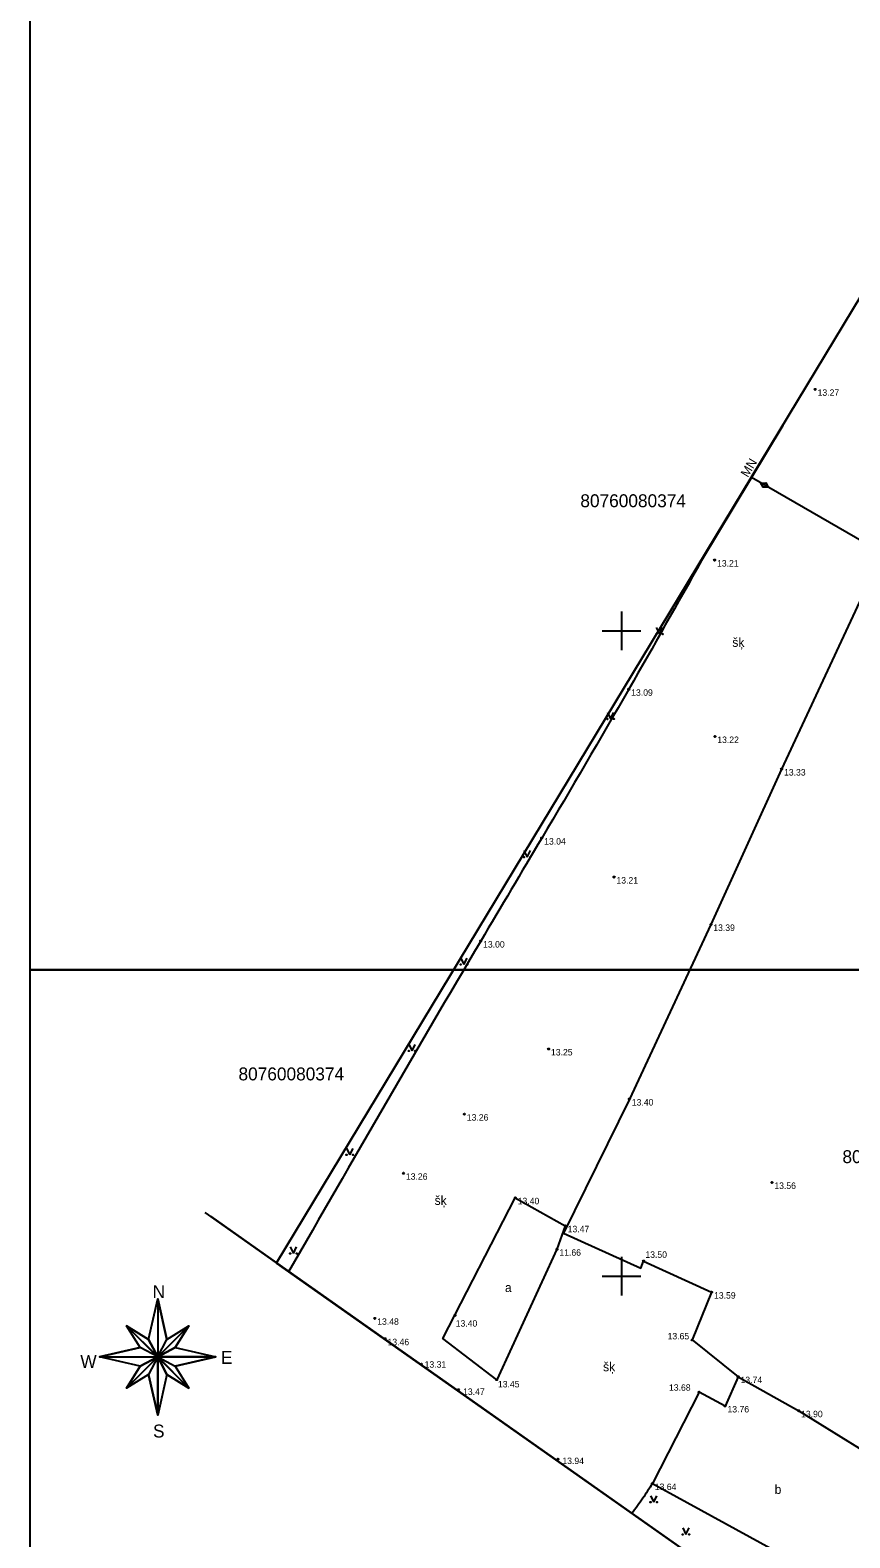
# Model space of a CAD drawing. Extents: x 503904 to 504094, y 304688 to 304960.
# Drawn here: x 503904.2 to 503967.7, y 304779.7 to 304896.6 of the extents above; entities that cross this region are included whole.
import ezdxf

# ---------------------------------------------------------------- set-up
doc = ezdxf.new("R2010")
doc.units = 0
for name, color, linetype in [('BUVE_EKAS_####_####_#', 7, 'Continuous'), ('BUVE_EKAS_RAKS_TKST_#', 7, 'Continuous'), ('CELI_CMAL_####_####_#', 7, 'Continuous'), ('CELI_CSEG_####_TKST_#', 7, 'Continuous'), ('CELI_TAKA_####_####_#', 7, 'Continuous'), ('GEOD_ELEM_####_####_#', 7, 'Continuous'), ('RAMI_PLAN_####_TKST_#', 7, 'Continuous'), ('RAMI_UZMR_####_####_#', 7, 'Continuous'), ('RELJ_AATZ_####_TKST_#', 7, 'Continuous'), ('RELJ_ELEM_####_####_#', 7, 'Continuous'), ('ROBZ_UZMR_####_####_#', 7, 'Continuous'), ('ROBZ_UZMR_####_TKST_#', 7, 'Continuous'), ('SAKT_ELEM_####_####_#', 7, 'Continuous'), ('SAKT_VADP_KABE_####_#', 7, 'Continuous'), ('TERT_ELEM_####_####_#', 7, 'Continuous')]:
    doc.layers.add(name, color=color, linetype=linetype)

msp = doc.modelspace()

# ---------------------------------------------------------------- linework, layer by layer
at = {"layer": 'BUVE_EKAS_####_####_#'}
for p, q in [((503962.51, 304865.92), (503956.21, 304855.46)), ((503962.5, 304865.93), (503962.51, 304865.92)), ((503956.21, 304855.46), (503956.18, 304855.48))]:
    msp.add_line(p, q, dxfattribs=at)
at = {"layer": 'CELI_CMAL_####_####_#'}
for points in [[(503988.45, 304902.16), (503990.82, 304901.05), (503991.1, 304895.95), (503989.73, 304890.94), (503987.1, 304886.1), (503981.04, 304876.47), (503973.97, 304864.11), (503962.41, 304839.3), (503956.93, 304827.26), (503950.62, 304813.73), (503945.51, 304803.34), (503951.5, 304800.63), (503951.72, 304801.18), (503956.99, 304798.77), (503955.48, 304795.07), (503959.04, 304792.22), (503963.73, 304789.58), (503971.68, 304784.66)], [(503941.78, 304806.08), (503945.65, 304803.91), (503945.01, 304802.09), (503940.34, 304791.99), (503936.17, 304795.17), (503941.78, 304806.08)], [(503959.04, 304792.22), (503958.03, 304789.95), (503956.01, 304791.02), (503952.4, 304783.94), (503962.64, 304778.33), (503962.54, 304778.05), (503967.21, 304775.56), (503967.57, 304775.37)]]:
    msp.add_lwpolyline(points, dxfattribs=at)
at = {"layer": 'CELI_TAKA_####_####_#'}
for points in [[(503956.21, 304855.46), (503950.57, 304845.48), (503943.83, 304833.95), (503939.1, 304825.97), (503924.21, 304800.34)], [(503952.4, 304783.94), (503951.66, 304782.81), (503950.81, 304781.61)]]:
    msp.add_spline(points, degree=3, dxfattribs=at)
at = {"layer": 'GEOD_ELEM_####_####_#'}
for p, q in [((503950, 304851.5), (503950, 304850)), ((503948.5, 304850), (503950, 304850)), ((503950, 304850), (503950, 304848.5)), ((503950, 304850), (503951.5, 304850)), ((503950, 304801.5), (503950, 304800)), ((503948.5, 304800), (503950, 304800)), ((503950, 304800), (503950, 304798.5)), ((503950, 304800), (503951.5, 304800))]:
    msp.add_line(p, q, dxfattribs=at)
at = {"layer": 'RAMI_PLAN_####_TKST_#'}
for p, q in [((503914.08, 304798.25), (503914.08, 304789.25)), ((503911.66, 304796.17), (503916.49, 304791.34)), ((503914.08, 304793.75), (503912.73, 304794.47)), ((503913.36, 304795.1), (503914.08, 304793.75)), ((503914.08, 304793.75), (503914.8, 304795.1)), ((503915.43, 304794.47), (503914.08, 304793.75)), ((503909.58, 304793.75), (503918.58, 304793.75)), ((503912.73, 304793.03), (503914.08, 304793.75)), ((503914.08, 304793.75), (503913.36, 304792.4)), ((503914.08, 304793.75), (503915.43, 304793.03)), ((503914.8, 304792.4), (503914.08, 304793.75))]:
    msp.add_line(p, q, dxfattribs=at)
for points in [[(503904.2, 304959.85), (504093.7, 304959.85), (504093.7, 304823.74), (503904.2, 304823.74)], [(503904.2, 304823.74), (504093.7, 304823.74), (504093.7, 304687.63), (503904.2, 304687.63)], [(503916.49, 304791.34), (503914.8, 304792.4), (503914.08, 304789.25), (503913.36, 304792.4), (503911.66, 304791.34), (503912.73, 304793.03), (503909.58, 304793.75), (503912.73, 304794.47), (503911.66, 304796.17), (503913.36, 304795.1), (503914.08, 304798.25), (503914.8, 304795.1), (503916.49, 304796.17), (503915.43, 304794.47), (503918.58, 304793.75), (503915.43, 304793.03)]]:
    msp.add_lwpolyline(points, close=True, dxfattribs=at)
for points in [[(503914.08, 304793.75), (503914.8, 304795.1), (503914.08, 304798.25), (503914.08, 304793.75)], [(503916.49, 304796.17), (503911.66, 304791.34)], [(503914.08, 304793.75), (503913.36, 304795.1), (503911.66, 304796.17), (503914.08, 304793.75)], [(503914.08, 304793.75), (503915.43, 304794.47), (503916.49, 304796.17), (503914.08, 304793.75)], [(503914.08, 304793.75), (503912.73, 304794.47), (503909.58, 304793.75), (503914.08, 304793.75)], [(503914.08, 304793.75), (503912.73, 304793.03), (503911.66, 304791.34), (503914.08, 304793.75)], [(503914.08, 304793.75), (503913.36, 304792.4), (503914.08, 304789.25), (503914.08, 304793.75)], [(503914.08, 304793.75), (503915.43, 304793.03), (503918.58, 304793.75), (503914.08, 304793.75)], [(503914.08, 304793.75), (503914.8, 304792.4), (503916.49, 304791.34), (503914.08, 304793.75)]]:
    msp.add_lwpolyline(points, dxfattribs=at)
at = {"layer": 'RAMI_UZMR_####_####_#'}
msp.add_lwpolyline([(503923.25, 304801.02), (503981.98, 304759.67), (503995.48, 304748.81), (504027.75, 304817.25), (504060.02, 304885.7), (504048.87, 304885.77), (504036.8, 304888.85), (503994.54, 304908.3), (503981.12, 304894.75), (503978.52, 304892.44), (503950.89, 304846.73), (503923.25, 304801.02)], dxfattribs=at)
at = {"layer": 'RELJ_ELEM_####_####_#'}
for centre in [(503965.01, 304868.72), (503957.22, 304855.49), (503950.57, 304845.48), (503957.24, 304841.82), (503962.41, 304839.3), (503943.83, 304833.95), (503949.43, 304830.93), (503956.93, 304827.26), (503939.1, 304825.97), (503944.36, 304817.61), (503950.62, 304813.73), (503937.84, 304812.56), (503933.12, 304807.98), (503961.66, 304807.27), (503941.78, 304806.08), (503945.65, 304803.91), (503945.01, 304802.09), (503951.72, 304801.18), (503956.99, 304798.77), (503930.9, 304796.74), (503937.11, 304796.97), (503931.7, 304795.16), (503955.48, 304795.07), (503934.51, 304793.19), (503940.34, 304791.99), (503959.04, 304792.22), (503937.38, 304791.21), (503956.01, 304791.02), (503958.03, 304789.95), (503963.73, 304789.58), (503945.08, 304785.83), (503952.4, 304783.94)]:
    msp.add_circle(centre, 0.05, dxfattribs=at)
at = {"layer": 'ROBZ_UZMR_####_####_#'}
for points in [[(503968.74, 304903.51), (503981.12, 304894.75), (503978.52, 304892.44), (503923.29, 304801.04), (503917.76, 304804.94)], [(503918.17, 304804.65), (503923.29, 304801.04), (503981.98, 304759.67), (503976.44, 304742.94)]]:
    msp.add_lwpolyline(points, dxfattribs=at)
msp.add_lwpolyline([(503923.29, 304801.04), (503978.52, 304892.44), (503981.12, 304894.75), (504030.46, 304860.12), (503981.98, 304759.67)], close=True, dxfattribs=at)
at = {"layer": 'SAKT_ELEM_####_####_#'}
msp.add_lwpolyline([(503960.81, 304861.46), (503961.18, 304861.47), (503961.36, 304861.14), (503960.98, 304861.13)], close=True, dxfattribs=at)
at = {"layer": 'SAKT_VADP_KABE_####_#'}
msp.add_lwpolyline([(504000.53, 304838.55), (503960.08, 304861.88)], dxfattribs=at)
at = {"layer": 'TERT_ELEM_####_####_#'}
for p, q in [((503952.7, 304850.26), (503952.95, 304849.76)), ((503952.95, 304849.76), (503953.2, 304850.26)), ((503948.91, 304843.68), (503949.16, 304843.18)), ((503949.16, 304843.18), (503949.41, 304843.68)), ((503942.45, 304832.98), (503942.7, 304832.48)), ((503942.7, 304832.48), (503942.95, 304832.98)), ((503937.55, 304824.66), (503937.8, 304824.16)), ((503937.8, 304824.16), (503938.05, 304824.66)), ((503933.53, 304817.96), (503933.78, 304817.46)), ((503933.78, 304817.46), (503934.03, 304817.96)), ((503928.71, 304809.91), (503928.96, 304809.41)), ((503928.96, 304809.41), (503929.21, 304809.91)), ((503924.34, 304802.27), (503924.59, 304801.77)), ((503924.59, 304801.77), (503924.84, 304802.27)), ((503952.25, 304783), (503952.5, 304782.5)), ((503952.5, 304782.5), (503952.75, 304783)), ((503954.75, 304780.5), (503955, 304780)), ((503955, 304780), (503955.25, 304780.5))]:
    msp.add_line(p, q, dxfattribs=at)
for centre, radius in [((503952.7, 304849.76), 0.028), ((503953.2, 304849.76), 0.0263), ((503948.91, 304843.18), 0.028), ((503949.41, 304843.18), 0.0263), ((503942.45, 304832.48), 0.028), ((503942.95, 304832.48), 0.0263), ((503937.55, 304824.16), 0.028), ((503938.05, 304824.16), 0.0263), ((503933.53, 304817.46), 0.028), ((503934.03, 304817.46), 0.0263), ((503928.71, 304809.41), 0.028), ((503929.21, 304809.41), 0.0263), ((503924.34, 304801.77), 0.028), ((503924.84, 304801.77), 0.0263), ((503952.25, 304782.5), 0.028), ((503952.75, 304782.5), 0.0263), ((503954.75, 304780), 0.028), ((503955.25, 304780), 0.0263)]:
    msp.add_circle(centre, radius, dxfattribs=at)

# ---------------------------------------------------------------- texts
at = {"layer": 'BUVE_EKAS_RAKS_TKST_#'}
msp.add_text('MN', height=0.7, rotation=58.8555, dxfattribs=at).set_placement((503959.79, 304861.85))
at = {"layer": 'CELI_CSEG_####_TKST_#'}
for s, p in [('šķ', (503958.59, 304848.77)), ('šķ', (503935.53, 304805.53)), ('a', (503940.98, 304798.78)), ('šķ', (503948.58, 304792.64)), ('b', (503961.87, 304783.14))]:
    msp.add_text(s, height=0.7, dxfattribs=at).set_placement(p)
at = {"layer": 'RAMI_PLAN_####_TKST_#'}
for s, p in [('N', (503913.69, 304798.31)), ('W', (503908.09, 304792.9)), ('E', (503918.98, 304793.21)), ('S', (503913.72, 304787.51))]:
    msp.add_text(s, height=1, dxfattribs=at).set_placement(p)
at = {"layer": 'RELJ_AATZ_####_TKST_#'}
for s, p in [(' 13.27', (503965.01, 304868.22)), (' 13.21', (503957.22, 304854.99)), (' 13.09', (503950.57, 304844.98)), (' 13.22', (503957.24, 304841.32)), (' 13.33', (503962.41, 304838.8)), (' 13.04', (503943.83, 304833.45)), (' 13.21', (503949.43, 304830.43)), (' 13.39', (503956.93, 304826.76)), (' 13.00', (503939.1, 304825.47)), (' 13.25', (503944.36, 304817.11)), (' 13.40', (503950.62, 304813.23)), (' 13.26', (503937.84, 304812.06)), (' 13.26', (503933.12, 304807.48)), (' 13.56', (503961.66, 304806.77)), (' 13.40', (503941.78, 304805.58)), (' 13.47', (503945.65, 304803.41)), (' 11.66', (503945.01, 304801.59)), (' 13.50', (503951.67, 304801.43)), (' 13.59', (503956.99, 304798.27)), (' 13.48', (503930.9, 304796.24)), (' 13.40', (503936.98, 304796.1)), (' 13.65', (503953.39, 304795.11)), (' 13.46', (503931.7, 304794.66)), (' 13.31', (503934.57, 304792.92)), (' 13.74', (503959.04, 304791.72)), (' 13.47', (503937.55, 304790.81)), (' 13.45', (503940.25, 304791.39)), (' 13.68', (503953.5, 304791.13)), (' 13.76', (503958.03, 304789.45)), (' 13.90', (503963.73, 304789.08)), (' 13.94', (503945.24, 304785.45)), (' 13.64', (503952.4, 304783.44))]:
    msp.add_text(s, height=0.5, dxfattribs=at).set_placement(p)
at = {"layer": 'ROBZ_UZMR_####_TKST_#'}
for s, p in [('80760080374', (503946.82, 304859.59)), ('80760080374', (503920.34, 304815.18)), ('80760080231', (503967.12, 304808.77))]:
    msp.add_text(s, height=1, dxfattribs=at).set_placement(p)

doc.saveas('drawing.dxf')
